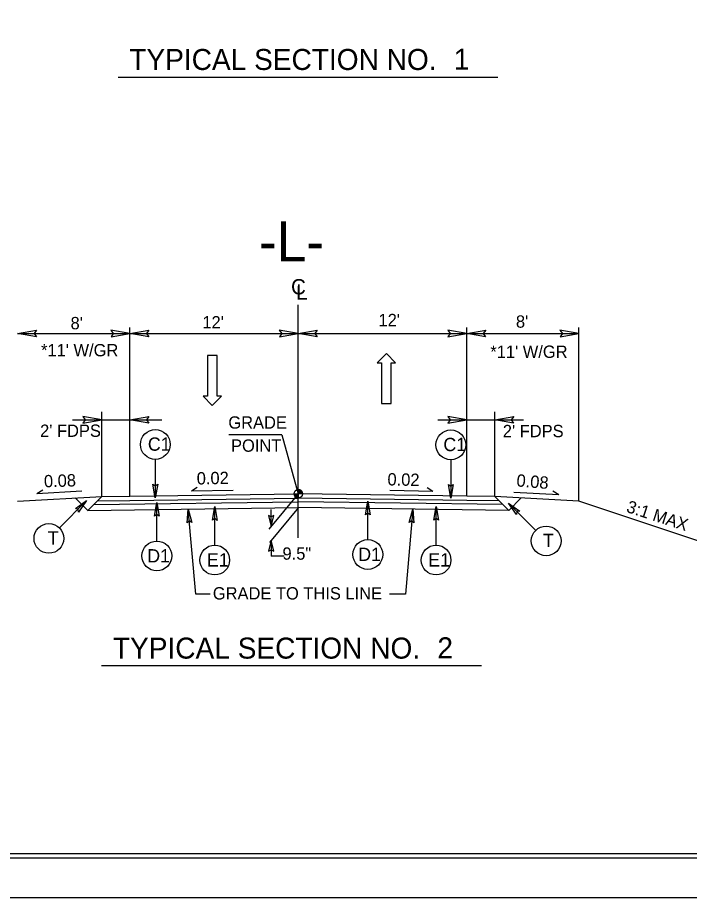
# Model space of a CAD drawing. Extents: x 1497225 to 1499181, y 579958 to 582278.
# Drawn here: x 1498169 to 1498551, y 581178 to 581678 of the extents above; entities that cross this region are included whole.
import ezdxf

# ---------------------------------------------------------------- set-up
doc = ezdxf.new("R2010")
doc.units = 0
for name, color, linetype in [('Old_Level_1', 7, 'Continuous'), ('Old_Level_11', 7, 'Continuous'), ('Old_Level_4', 7, 'Continuous'), ('Prop Dimension Text', 7, 'Continuous'), ('Sheet Cutting Line CELL', 7, 'Continuous'), ('Sheet Plot Border Inside CELL', 7, 'Continuous'), ('Sheet Plot Border Outside CELL', 7, 'Continuous'), ('Sheet Typical CELL', 7, 'Continuous'), ('Typical ID Circle CELL', 7, 'Continuous'), ('Typical Terminator CELL', 7, 'Continuous'), ('Typical Text ID Circle CELL', 7, 'Continuous'), ('Typical Text Label CELL', 7, 'Continuous')]:
    doc.layers.add(name, color=color, linetype=linetype)

# ---------------------------------------------------------------- blocks, each defined once
blk = doc.blocks.new('TERMINATOR')
at = {"layer": 'Typical Terminator CELL'}
blk.add_lwpolyline([(-0.469, 0.081), (0, 0), (-0.471, -0.083), (-0.411, 0)], close=True, dxfattribs=at)

msp = doc.modelspace()

# ---------------------------------------------------------------- linework, layer by layer
at = {"layer": 'Old_Level_1'}
for p, q in [((1498328.14, 581382.41), (1498328.14, 581514.74)), ((1498168.53, 581498.49), (1498232.38, 581498.49)), ((1498232.38, 581406.09), (1498232.38, 581501.93)), ((1498232.38, 581498.49), (1498328.14, 581498.49)), ((1498328.14, 581498.49), (1498423.91, 581498.49)), ((1498423.91, 581406.09), (1498423.91, 581501.93)), ((1498423.91, 581498.49), (1498487.76, 581498.49)), ((1498487.76, 581403.22), (1498487.76, 581501.93)), ((1498216.42, 581405.88), (1498216.42, 581454.03)), ((1498439.87, 581405.87), (1498439.87, 581454.03)), ((1498199.7, 581449.38), (1498250.53, 581449.38)), ((1498216.42, 581449.38), (1498232.38, 581449.38)), ((1498407.59, 581449.38), (1498456.28, 581449.38)), ((1498423.91, 581449.38), (1498439.87, 581449.38)), ((1498318.74, 581440.97), (1498288.75, 581440.97)), ((1498318.74, 581440.97), (1498328.14, 581407.37)), ((1498179.47, 581407.61), (1498182.85, 581409.65)), ((1498179.47, 581407.61), (1498204.99, 581408.98)), ((1498232.38, 581406.09), (1498328.14, 581407.37)), ((1498267.34, 581409.05), (1498270.71, 581411.09)), ((1498267.34, 581409.05), (1498291.16, 581409.53)), ((1498328.14, 581407.37), (1498311.38, 581387.2)), ((1498325.76, 581407.37), (1498328.14, 581407.37)), ((1498328.14, 581407.37), (1498328.14, 581409.75)), ((1498423.91, 581406.09), (1498328.14, 581407.37)), ((1498330.53, 581407.37), (1498328.14, 581407.37)), ((1498328.14, 581404.99), (1498328.14, 581407.37)), ((1498328.14, 581407.37), (1498328.14, 581404.99)), ((1498404.72, 581408.72), (1498380.21, 581409.21)), ((1498404.72, 581408.72), (1498401.35, 581410.76)), ((1498450.8, 581408.34), (1498476.32, 581406.97)), ((1498472.95, 581409.01), (1498476.32, 581406.97)), ((1498168.53, 581403.22), (1498216.42, 581405.87)), ((1498201.33, 581405.04), (1498208.45, 581397.91)), ((1498208.45, 581397.91), (1498216.42, 581405.87)), ((1498211.8, 581401.26), (1498328.14, 581402.85)), ((1498213.9, 581403.36), (1498232.38, 581403.61)), ((1498216.42, 581405.87), (1498232.38, 581406.09)), ((1498232.38, 581403.61), (1498328.14, 581404.89)), ((1498423.91, 581403.61), (1498328.14, 581404.89)), ((1498444.48, 581401.26), (1498328.14, 581402.85)), ((1498439.87, 581405.87), (1498423.91, 581406.09)), ((1498442.38, 581403.36), (1498423.91, 581403.61)), ((1498487.76, 581403.22), (1498439.87, 581405.87)), ((1498439.87, 581405.87), (1498447.83, 581397.91)), ((1498447.83, 581397.91), (1498454.95, 581405.04)), ((1498573.97, 581374.48), (1498487.76, 581403.22)), ((1498208.45, 581397.91), (1498328.14, 581399.55)), ((1498269.8, 581350.4), (1498265.57, 581398.69)), ((1498328.25, 581399.52), (1498311.72, 581379.64)), ((1498312.7, 581388.79), (1498312.7, 581398.42)), ((1498447.83, 581397.91), (1498328.14, 581399.55)), ((1498393.25, 581398.69), (1498389.03, 581350.4)), ((1498312.81, 581380.94), (1498312.81, 581371.95)), ((1498320.11, 581371.95), (1498312.81, 581371.95)), ((1498278.11, 581350.4), (1498269.8, 581350.4)), ((1498389.03, 581350.4), (1498380.08, 581350.4))]:
    msp.add_line(p, q, dxfattribs=at)
for points in [[(1498325.77, 581407.37), (1498325.77, 581407.11)], [(1498325.82, 581407.37), (1498325.82, 581406.83)], [(1498325.87, 581407.37), (1498325.87, 581406.66)], [(1498325.91, 581407.37), (1498325.91, 581406.52)], [(1498325.96, 581407.37), (1498325.96, 581406.41)], [(1498326.01, 581407.37), (1498326.01, 581406.31)], [(1498326.06, 581407.37), (1498326.06, 581406.22)], [(1498326.1, 581407.37), (1498326.1, 581406.13)], [(1498326.15, 581407.37), (1498326.15, 581406.06)], [(1498326.2, 581407.37), (1498326.2, 581405.99)], [(1498326.25, 581407.37), (1498326.25, 581405.92)], [(1498326.3, 581407.37), (1498326.3, 581405.87)], [(1498326.34, 581407.37), (1498326.34, 581405.81)], [(1498326.39, 581407.37), (1498326.39, 581405.76)], [(1498326.44, 581407.37), (1498326.44, 581405.7)], [(1498326.49, 581407.37), (1498326.49, 581405.65)], [(1498326.53, 581407.37), (1498326.53, 581405.61)], [(1498326.58, 581407.37), (1498326.58, 581405.57)], [(1498326.63, 581407.37), (1498326.63, 581405.53)], [(1498326.68, 581407.37), (1498326.68, 581405.49)], [(1498326.72, 581407.37), (1498326.72, 581405.45)], [(1498326.77, 581407.37), (1498326.77, 581405.42)], [(1498326.82, 581407.37), (1498326.82, 581405.39)], [(1498326.87, 581407.37), (1498326.87, 581405.36)], [(1498326.91, 581407.37), (1498326.91, 581405.33)], [(1498326.96, 581407.37), (1498326.96, 581405.3)], [(1498327.01, 581407.37), (1498327.01, 581405.27)], [(1498327.06, 581407.37), (1498327.06, 581405.25)], [(1498327.11, 581407.37), (1498327.11, 581405.23)], [(1498327.15, 581407.37), (1498327.15, 581405.2)], [(1498327.2, 581407.37), (1498327.2, 581405.18)], [(1498327.25, 581407.37), (1498327.25, 581405.16)], [(1498327.3, 581407.37), (1498327.3, 581405.14)], [(1498327.34, 581407.37), (1498327.34, 581405.13)], [(1498327.39, 581407.37), (1498327.39, 581405.11)], [(1498327.44, 581407.37), (1498327.44, 581405.09)], [(1498327.49, 581407.37), (1498327.49, 581405.08)], [(1498327.53, 581407.37), (1498327.53, 581405.07)], [(1498327.58, 581407.37), (1498327.58, 581405.06)], [(1498327.63, 581407.37), (1498327.63, 581405.05)], [(1498327.68, 581407.37), (1498327.68, 581405.04)], [(1498327.72, 581407.37), (1498327.72, 581405.02)], [(1498327.77, 581407.37), (1498327.77, 581405.02)], [(1498327.82, 581407.37), (1498327.82, 581405.01)], [(1498327.87, 581407.37), (1498327.87, 581405)], [(1498327.92, 581407.37), (1498327.92, 581405)], [(1498327.96, 581407.37), (1498327.96, 581404.99)], [(1498328.01, 581407.37), (1498328.01, 581404.99)], [(1498328.06, 581407.37), (1498328.06, 581404.99)], [(1498328.11, 581407.37), (1498328.11, 581404.99), (1498328.11, 581404.99)], [(1498328.16, 581409.75), (1498328.16, 581409.75), (1498328.16, 581407.37)], [(1498328.21, 581409.75), (1498328.21, 581407.37)], [(1498328.26, 581409.75), (1498328.26, 581407.37)], [(1498328.31, 581409.75), (1498328.31, 581407.37)], [(1498328.36, 581409.74), (1498328.36, 581407.37)], [(1498328.4, 581409.74), (1498328.4, 581407.37)], [(1498328.45, 581409.73), (1498328.45, 581407.37)], [(1498328.5, 581409.73), (1498328.5, 581407.37)], [(1498328.55, 581409.72), (1498328.55, 581407.37)], [(1498328.59, 581409.71), (1498328.59, 581407.37)], [(1498328.64, 581409.7), (1498328.64, 581407.37)], [(1498328.69, 581409.69), (1498328.69, 581407.37)], [(1498328.74, 581409.68), (1498328.74, 581407.37)], [(1498328.78, 581409.66), (1498328.78, 581407.37)], [(1498328.83, 581409.65), (1498328.83, 581407.37)], [(1498328.88, 581409.64), (1498328.88, 581407.37)], [(1498328.93, 581409.62), (1498328.93, 581407.37)], [(1498328.97, 581409.6), (1498328.97, 581407.37)], [(1498329.02, 581409.58), (1498329.02, 581407.37)], [(1498329.07, 581409.56), (1498329.07, 581407.37)], [(1498329.12, 581409.54), (1498329.12, 581407.37)], [(1498329.17, 581409.52), (1498329.17, 581407.37)], [(1498329.21, 581409.5), (1498329.21, 581407.37)], [(1498329.26, 581409.47), (1498329.26, 581407.37)], [(1498329.31, 581409.44), (1498329.31, 581407.37)], [(1498329.36, 581409.42), (1498329.36, 581407.37)], [(1498329.4, 581409.39), (1498329.4, 581407.37)], [(1498329.45, 581409.36), (1498329.45, 581407.37)], [(1498329.5, 581409.33), (1498329.5, 581407.37)], [(1498329.55, 581409.29), (1498329.55, 581407.37)], [(1498329.59, 581409.26), (1498329.59, 581407.37)], [(1498329.64, 581409.22), (1498329.64, 581407.37)], [(1498329.69, 581409.18), (1498329.69, 581407.37)], [(1498329.74, 581409.14), (1498329.74, 581407.37)], [(1498329.79, 581409.1), (1498329.79, 581407.37)], [(1498329.83, 581409.05), (1498329.83, 581407.37)], [(1498329.88, 581409), (1498329.88, 581407.37)], [(1498329.93, 581408.95), (1498329.93, 581407.37)], [(1498329.98, 581408.89), (1498329.98, 581407.37)], [(1498330.02, 581408.83), (1498330.02, 581407.37)], [(1498330.07, 581408.77), (1498330.07, 581407.37)], [(1498330.12, 581408.7), (1498330.12, 581407.37)], [(1498330.17, 581408.62), (1498330.17, 581407.37)], [(1498330.21, 581408.54), (1498330.21, 581407.37)], [(1498330.26, 581408.46), (1498330.26, 581407.37)], [(1498330.31, 581408.36), (1498330.31, 581407.37)], [(1498330.36, 581408.25), (1498330.36, 581407.37)], [(1498330.4, 581408.12), (1498330.4, 581407.37)], [(1498330.45, 581407.95), (1498330.45, 581407.37)], [(1498330.5, 581407.71), (1498330.5, 581407.37)]]:
    msp.add_lwpolyline(points, dxfattribs=at)
msp.add_ellipse((1498328.14, 581407.37), major_axis=(2.38, 0), ratio=0.9995, dxfattribs=at)
for major_axis in [(-2.38, 0), (2.38, 0)]:
    msp.add_ellipse((1498328.14, 581407.37), major_axis=major_axis, ratio=0.9995, start_param=6.283019, end_param=7.853815, dxfattribs=at)
at = {"layer": 'Old_Level_11'}
for points in [[(1498179.26, 581496.61), (1498168.53, 581498.49), (1498179.34, 581500.38), (1498177.97, 581498.49)], [(1498221.66, 581496.61), (1498232.38, 581498.49), (1498221.57, 581500.38), (1498222.94, 581498.49)], [(1498243.11, 581496.61), (1498232.38, 581498.49), (1498243.19, 581500.38), (1498241.82, 581498.49)], [(1498317.42, 581496.61), (1498328.14, 581498.49), (1498317.33, 581500.38), (1498318.71, 581498.49)], [(1498338.87, 581496.61), (1498328.14, 581498.49), (1498338.95, 581500.38), (1498337.58, 581498.49)], [(1498413.18, 581496.61), (1498423.91, 581498.49), (1498413.1, 581500.38), (1498414.47, 581498.49)], [(1498434.63, 581496.61), (1498423.91, 581498.49), (1498434.72, 581500.38), (1498433.34, 581498.49)], [(1498477.03, 581496.61), (1498487.76, 581498.49), (1498476.95, 581500.38), (1498478.32, 581498.49)], [(1498205.69, 581447.49), (1498216.42, 581449.38), (1498205.61, 581451.26), (1498206.98, 581449.38)], [(1498243.11, 581447.49), (1498232.38, 581449.38), (1498243.19, 581451.26), (1498241.82, 581449.38)], [(1498413.18, 581447.49), (1498423.91, 581449.38), (1498413.1, 581451.26), (1498414.47, 581449.38)], [(1498450.59, 581447.49), (1498439.87, 581449.38), (1498450.68, 581451.26), (1498449.3, 581449.38)]]:
    msp.add_lwpolyline(points, close=True, dxfattribs=at)
at = {"layer": 'Old_Level_4'}
for p, q in [((1498276.56, 581485.91), (1498276.56, 581462.81)), ((1498282.01, 581485.91), (1498276.56, 581485.91)), ((1498282.01, 581462.81), (1498282.01, 581485.91)), ((1498378.36, 581487.06), (1498373.08, 581481.86)), ((1498383.48, 581481.86), (1498378.36, 581487.06)), ((1498373.08, 581481.86), (1498375.56, 581481.86)), ((1498375.56, 581481.86), (1498375.56, 581458.76)), ((1498381, 581458.76), (1498381, 581481.86)), ((1498381, 581481.86), (1498383.48, 581481.86)), ((1498276.56, 581462.81), (1498274.09, 581462.81)), ((1498274.09, 581462.81), (1498279.2, 581457.61)), ((1498279.2, 581457.61), (1498284.48, 581462.81)), ((1498284.48, 581462.81), (1498282.01, 581462.81)), ((1498375.56, 581458.76), (1498381, 581458.76))]:
    msp.add_line(p, q, dxfattribs=at)
for points in [[(1498264.92, 581390.87), (1498265.57, 581398.69), (1498267.62, 581391.07), (1498266.16, 581391.93)], [(1498391.25, 581391.11), (1498393.25, 581398.69), (1498393.95, 581390.83), (1498392.66, 581391.93)]]:
    msp.add_lwpolyline(points, close=True, dxfattribs=at)
at = {"layer": 'Sheet Cutting Line CELL'}
msp.add_line((1497225.23, 581177.96), (1498909.23, 581177.96), dxfattribs=at)
at = {"layer": 'Sheet Plot Border Inside CELL'}
msp.add_lwpolyline([(1498904.73, 582255.51), (1497238.23, 582255.51), (1497238.23, 581200.41), (1498904.73, 581200.41)], close=True, dxfattribs=at)
at = {"layer": 'Sheet Plot Border Outside CELL'}
msp.add_lwpolyline([(1498909.23, 582277.96), (1497225.23, 582277.96), (1497225.23, 581177.96), (1498909.23, 581177.96)], close=True, dxfattribs=at)
at = {"layer": 'Sheet Typical CELL'}
msp.add_lwpolyline([(1498892.23, 582252.96), (1497392.23, 582252.96), (1497392.23, 581202.96), (1498892.23, 581202.96)], close=True, dxfattribs=at)
at = {"layer": 'Typical ID Circle CELL'}
for p, q in [((1498246.86, 581426.95), (1498246.86, 581405.08)), ((1498414.9, 581426.72), (1498414.9, 581404.85)), ((1498192.32, 581388.01), (1498207.79, 581403.48)), ((1498247.72, 581380.5), (1498247.72, 581402.37)), ((1498367.71, 581381.34), (1498367.71, 581403.21)), ((1498280.63, 581378.19), (1498280.63, 581400.06)), ((1498406.49, 581378.19), (1498406.49, 581400.07)), ((1498463.15, 581386.56), (1498447.68, 581402.02))]:
    msp.add_line(p, q, dxfattribs=at)
for centre in [(1498246.86, 581435.41), (1498414.9, 581435.18), (1498186.34, 581382.03), (1498469.13, 581380.57), (1498247.72, 581372.04), (1498280.63, 581369.72), (1498367.71, 581372.88), (1498406.49, 581369.73)]:
    msp.add_circle(centre, 8.46, dxfattribs=at)
at = {"layer": 'Typical Terminator CELL'}
for points in [[(1498248.19, 581412.81), (1498246.86, 581405.08), (1498245.48, 581412.85), (1498246.86, 581411.87)], [(1498416.23, 581412.58), (1498414.9, 581404.85), (1498413.52, 581412.63), (1498414.9, 581411.64)], [(1498201.38, 581398.95), (1498207.79, 581403.48), (1498203.26, 581397.01), (1498202.99, 581398.68)], [(1498246.39, 581394.64), (1498247.72, 581402.37), (1498249.09, 581394.59), (1498247.72, 581395.58)], [(1498366.38, 581395.48), (1498367.71, 581403.21), (1498369.08, 581395.43), (1498367.71, 581396.42)], [(1498279.29, 581392.32), (1498280.63, 581400.06), (1498282, 581392.28), (1498280.63, 581393.27)], [(1498405.16, 581392.33), (1498406.49, 581400.07), (1498407.86, 581392.29), (1498406.49, 581393.28)], [(1498452.21, 581395.61), (1498447.68, 581402.02), (1498454.15, 581397.49), (1498452.48, 581397.22)]]:
    msp.add_lwpolyline(points, close=True, dxfattribs=at)
at = {"layer": 'Typical Text Label CELL'}
for p, q in [((1498225.65, 581644.28), (1498441.69, 581644.28)), ((1498216.32, 581309.69), (1498432.37, 581309.69))]:
    msp.add_line(p, q, dxfattribs=at)

# ---------------------------------------------------------------- block references
at = {"layer": 'Old_Level_4', "xscale": 13.123011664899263, "yscale": -18.835616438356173}
for p, rotation in [((1498312.7, 581388.79), -89.99999999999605), ((1498312.81, 581380.94), 90.00000000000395)]:
    msp.add_blockref('TERMINATOR', p, dxfattribs=dict(at, rotation=rotation))

# ---------------------------------------------------------------- texts
at = {"layer": 'Old_Level_1'}
for s, height, rotation, p in [('-L-', 22.68, 359.9492, (1498305.74, 581539.51)), ('L', 8.73, 359.9469, (1498326.93, 581517.72)), ('0.08', 7, 2.0686, (1498183.64, 581410.99)), ('0.02', 7, 1.1457, (1498270.47, 581412.63)), ('0.02', 7, 358.8543, (1498378.82, 581412.16)), ('0.08', 7, 355.2385, (1498452.03, 581411.6)), ('3:1 MAX', 7, 342.1124, (1498514.27, 581397.16))]:
    msp.add_text(s, height=height, rotation=rotation, dxfattribs=at).set_placement(p)
for s, height, p in [('C', 8.73, (1498324.03, 581520.7)), ("8'", 7, (1498198.66, 581500.89)), ("12'", 7, (1498273.61, 581501.37)), ("12'", 7, (1498373.78, 581502.65)), ("8'", 7, (1498451.92, 581501.79)), ("*11' W/GR", 7, (1498181.9, 581485.51)), ("*11' W/GR", 7, (1498437.37, 581484.63)), ("2' FDPS", 7, (1498181.34, 581439.73)), ("2' FDPS", 7, (1498444.47, 581439.55)), ('GRADE TO THIS LINE', 7, (1498279.56, 581347.29))]:
    msp.add_text(s, height=height, dxfattribs=at).set_placement(p)
at = {"layer": 'Old_Level_4'}
msp.add_text('9.5"', height=7, rotation=360, dxfattribs=at).set_placement((1498319.17, 581369.91))
at = {"layer": 'Prop Dimension Text'}
for s, p in [('GRADE', (1498288.38, 581444.4)), ('POINT', (1498289.91, 581431.28))]:
    msp.add_text(s, height=7, rotation=0.0001, dxfattribs=at).set_placement(p)
at = {"layer": 'Typical Text ID Circle CELL'}
for s, height, p in [('C1', 7.575, (1498242.61, 581431.84)), ('C1', 7.575, (1498410.65, 581431.61)), ('T', 7.58, (1498185.69, 581378.54)), ('T', 7.58, (1498467.26, 581377.08)), ('D1', 7.575, (1498242.26, 581368.34)), ('E1', 7.575, (1498276.19, 581366.03)), ('D1', 7.575, (1498362.25, 581369.18)), ('E1', 7.575, (1498402.06, 581366.04))]:
    msp.add_text(s, height=height, dxfattribs=at).set_placement(p)
at = {"layer": 'Typical Text Label CELL'}
for s, height, p in [('TYPICAL SECTION NO.  ', 11.9356, (1498232.06, 581648.28)), ('1', 11.94, (1498416.58, 581648.44)), ('TYPICAL SECTION NO.  ', 11.9356, (1498222.73, 581313.69)), ('2', 11.94, (1498407.25, 581313.85))]:
    msp.add_text(s, height=height, dxfattribs=at).set_placement(p)

doc.saveas('drawing.dxf')
